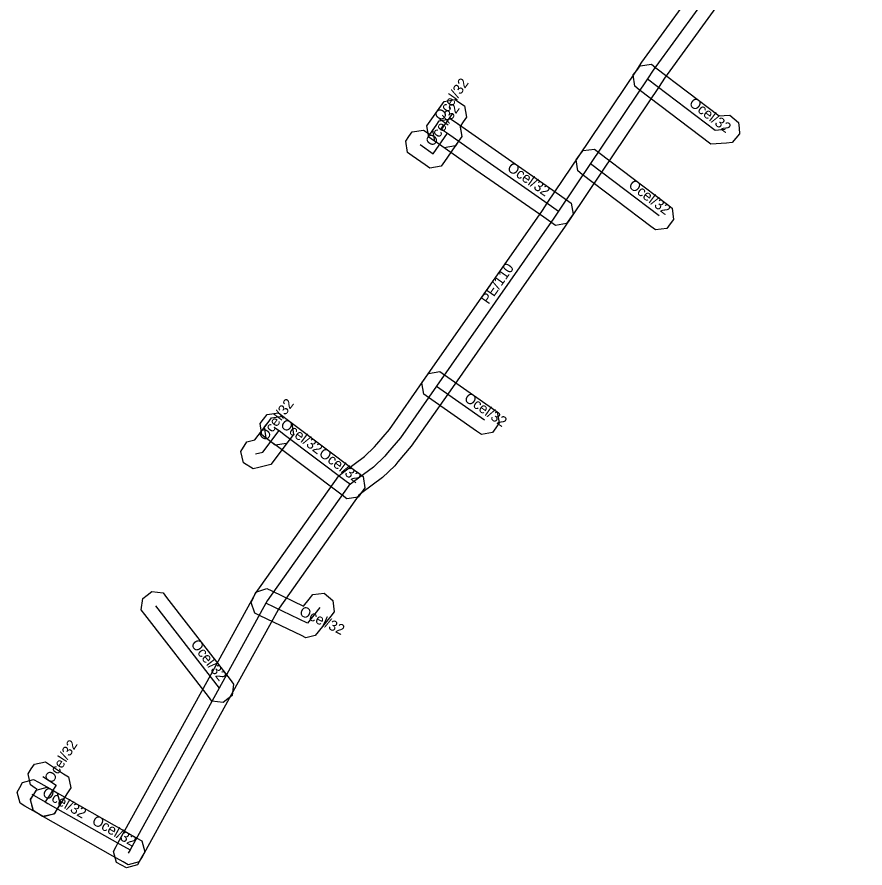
# Model space of a CAD drawing. Extents: x -600607 to -600238, y -1203924 to -1203617.
# Drawn here: x -600383.3 to -600321.7, y -1203772.2 to -1203710.4 of the extents above; entities that cross this region are included whole.
import ezdxf

# ---------------------------------------------------------------- set-up
doc = ezdxf.new("R2010")
doc.units = 0
for name, color, linetype in [('1', 7, 'Continuous'), ('14', 7, 'Continuous'), ('20', 7, 'Continuous')]:
    doc.layers.add(name, color=color, linetype=linetype)

msp = doc.modelspace()

# ---------------------------------------------------------------- linework, layer by layer
at = {"layer": '1'}
msp.add_lwpolyline([(-600329.759, -1203705.902), (-600336.238, -1203714.83), (-600336.638, -1203715.435), (-600340.78, -1203721.588), (-600343.101, -1203725.04), (-600343.466, -1203725.577), (-600351.98, -1203737.763), (-600354.628, -1203741.553), (-600355.596, -1203742.685), (-600355.827, -1203742.962), (-600356.722, -1203743.824), (-600358.216, -1203744.937), (-600358.434, -1203745.106), (-600358.437, -1203745.108), (-600364.232, -1203753.303), (-600364.305, -1203753.434), (-600367.694, -1203759.583), (-600374.177, -1203771.338), (-600374.309, -1203771.572), (-600374.513, -1203771.933), (-600375.311, -1203772.155), (-600375.672, -1203771.951), (-600376.033, -1203771.747), (-600376.255, -1203770.949), (-600376.051, -1203770.588), (-600375.923, -1203770.362), (-600369.446, -1203758.617), (-600366.055, -1203752.466), (-600365.928, -1203752.237), (-600359.886, -1203743.694), (-600359.646, -1203743.514), (-600359.424, -1203743.343), (-600358.018, -1203742.296), (-600357.293, -1203741.598), (-600357.124, -1203741.395), (-600356.212, -1203740.327), (-600353.62, -1203736.617), (-600345.114, -1203724.443), (-600344.759, -1203723.92), (-600342.44, -1203720.472), (-600338.302, -1203714.325), (-600337.882, -1203713.69), (-600331.401, -1203704.758)], dxfattribs=at)
for points in [[(-600337.194, -1203713.833), (-600336.864, -1203714.084), (-600332.269, -1203717.582), (-600331.911, -1203717.553), (-600331.498, -1203717.519), (-600330.867, -1203718.056), (-600330.833, -1203718.469), (-600330.799, -1203718.882), (-600331.336, -1203719.513), (-600331.749, -1203719.547), (-600332.871, -1203719.638), (-600338.076, -1203715.676), (-600338.405, -1203715.425), (-600338.517, -1203714.604), (-600338.266, -1203714.274), (-600338.015, -1203713.945)], [(-600350.851, -1203718.013), (-600351.083, -1203718.344), (-600350.953, -1203719.072), (-600351.19, -1203719.412), (-600351.427, -1203719.752), (-600352.242, -1203719.897), (-600352.582, -1203719.66), (-600353.012, -1203719.36), (-600353.352, -1203719.123), (-600353.425, -1203718.715), (-600353.497, -1203718.306), (-600353.259, -1203717.967), (-600352.489, -1203716.867), (-600352.252, -1203716.527), (-600351.436, -1203716.383), (-600351.097, -1203716.621), (-600350.757, -1203716.858), (-600350.613, -1203717.674)], [(-600353.744, -1203718.604), (-600353.405, -1203718.842), (-600353.287, -1203718.925), (-600352.831, -1203718.269), (-600352.594, -1203717.929), (-600351.779, -1203717.782), (-600351.439, -1203718.019), (-600351.099, -1203718.256), (-600350.952, -1203719.071), (-600351.189, -1203719.411), (-600352.219, -1203720.891), (-600352.457, -1203721.232), (-600352.866, -1203721.305), (-600353.275, -1203721.377), (-600353.615, -1203721.138), (-600354.555, -1203720.478), (-600354.894, -1203720.24), (-600355.036, -1203719.424), (-600354.798, -1203719.085), (-600354.56, -1203718.746)], [(-600351.778, -1203717.783), (-600351.438, -1203718.02), (-600348.788, -1203719.87), (-600343.866, -1203723.301), (-600343.353, -1203723.663), (-600343.015, -1203723.902), (-600342.874, -1203724.719), (-600343.113, -1203725.057), (-600343.352, -1203725.395), (-600344.169, -1203725.536), (-600344.507, -1203725.297), (-600345.014, -1203724.939), (-600349.932, -1203721.51), (-600352.582, -1203719.66), (-600352.922, -1203719.423), (-600353.067, -1203718.608), (-600352.83, -1203718.268), (-600352.593, -1203717.928)], [(-600341.335, -1203719.983), (-600341.005, -1203720.233), (-600336.025, -1203724.013), (-600335.695, -1203724.264), (-600335.583, -1203725.085), (-600335.833, -1203725.415), (-600336.084, -1203725.745), (-600336.905, -1203725.857), (-600337.235, -1203725.607), (-600342.215, -1203721.827), (-600342.545, -1203721.576), (-600342.657, -1203720.755), (-600342.407, -1203720.425), (-600342.156, -1203720.095)], [(-600352.567, -1203736.133), (-600352.227, -1203736.37), (-600348.737, -1203738.81), (-600348.397, -1203739.047), (-600348.253, -1203739.863), (-600348.49, -1203740.203), (-600348.727, -1203740.543), (-600349.543, -1203740.687), (-600349.883, -1203740.45), (-600353.373, -1203738.01), (-600353.713, -1203737.773), (-600353.857, -1203736.957), (-600353.62, -1203736.617), (-600353.383, -1203736.277)], [(-600364.281, -1203739.131), (-600363.95, -1203739.38), (-600363.63, -1203739.62), (-600363.299, -1203739.869), (-600363.181, -1203740.689), (-600363.43, -1203741.02), (-600363.679, -1203741.351), (-600364.499, -1203741.469), (-600364.83, -1203741.22), (-600365.15, -1203740.98), (-600365.481, -1203740.731), (-600365.599, -1203739.911), (-600365.35, -1203739.58), (-600365.101, -1203739.249)], [(-600366.577, -1203741.235), (-600366.174, -1203741.138), (-600365.984, -1203741.092), (-600365.03, -1203739.82), (-600364.781, -1203739.489), (-600363.961, -1203739.371), (-600363.63, -1203739.62), (-600363.299, -1203739.869), (-600363.181, -1203740.689), (-600363.43, -1203741.02), (-600364.816, -1203742.868), (-600365.706, -1203743.082), (-600366.109, -1203743.179), (-600366.815, -1203742.747), (-600366.912, -1203742.344), (-600367.009, -1203741.941)], [(-600363.961, -1203739.371), (-600363.63, -1203739.62), (-600363.15, -1203739.98), (-600358.752, -1203743.278), (-600358.444, -1203743.507), (-600358.111, -1203743.754), (-600357.99, -1203744.573), (-600358.237, -1203744.906), (-600358.484, -1203745.239), (-600359.303, -1203745.36), (-600359.636, -1203745.113), (-600359.948, -1203744.882), (-600364.35, -1203741.58), (-600364.83, -1203741.22), (-600365.161, -1203740.971), (-600365.279, -1203740.151), (-600365.03, -1203739.82), (-600364.781, -1203739.489)], [(-600372.653, -1203752.2), (-600372.4, -1203752.527), (-600367.78, -1203758.487), (-600367.526, -1203758.815), (-600367.63, -1203759.637), (-600367.957, -1203759.89), (-600368.285, -1203760.144), (-600369.107, -1203760.04), (-600369.36, -1203759.713), (-600373.98, -1203753.753), (-600374.234, -1203753.425), (-600374.13, -1203752.603), (-600373.803, -1203752.35), (-600373.475, -1203752.096)], [(-600360.22, -1203753.559), (-600360.478, -1203753.883), (-600361.378, -1203755.013), (-600361.595, -1203755.286), (-600362.275, -1203755.443), (-600362.59, -1203755.293), (-600365.61, -1203753.853), (-600365.984, -1203753.674), (-600366.261, -1203752.894), (-600366.083, -1203752.52), (-600365.904, -1203752.146), (-600365.124, -1203751.869), (-600364.75, -1203752.047), (-600362.447, -1203753.145), (-600362.042, -1203752.637), (-600361.784, -1203752.313), (-600360.961, -1203752.22), (-600360.637, -1203752.478), (-600360.313, -1203752.736)], [(-600381.177, -1203764.457), (-600380.831, -1203764.684), (-600379.871, -1203765.314), (-600379.527, -1203765.54), (-600379.356, -1203766.346), (-600379.579, -1203766.692), (-600380.359, -1203767.902), (-600380.584, -1203768.25), (-600381.394, -1203768.425), (-600381.742, -1203768.201), (-600382.09, -1203767.976), (-600382.265, -1203767.166), (-600382.041, -1203766.818), (-600381.798, -1203766.442), (-600381.929, -1203766.356), (-600382.275, -1203766.129), (-600382.443, -1203765.317), (-600382.216, -1203764.971), (-600381.989, -1203764.625)], [(-600382.044, -1203765.727), (-600381.684, -1203765.932), (-600380.704, -1203766.492), (-600380.344, -1203766.697), (-600380.127, -1203767.496), (-600380.332, -1203767.856), (-600380.537, -1203768.216), (-600381.336, -1203768.433), (-600381.696, -1203768.228), (-600382.676, -1203767.668), (-600383.036, -1203767.463), (-600383.253, -1203766.664), (-600383.048, -1203766.304), (-600382.843, -1203765.944)], [(-600381.057, -1203766.287), (-600380.699, -1203766.495), (-600380.513, -1203766.602), (-600375.293, -1203769.552), (-600374.548, -1203769.985), (-600374.19, -1203770.193), (-600373.977, -1203770.994), (-600374.185, -1203771.352), (-600374.393, -1203771.71), (-600375.194, -1203771.923), (-600375.552, -1203771.715), (-600376.287, -1203771.288), (-600381.507, -1203768.338), (-600381.701, -1203768.225), (-600382.059, -1203768.017), (-600382.273, -1203767.217), (-600382.065, -1203766.859), (-600381.857, -1203766.501)]]:
    msp.add_lwpolyline(points, close=True, dxfattribs=at)
at = {"layer": '14'}
for points in [[(-600321.69, -1203692.03), (-600330.58, -1203705.33), (-600337.06, -1203714.26), (-600337.47, -1203714.88), (-600341.61, -1203721.03), (-600343.93, -1203724.48), (-600344.29, -1203725.01), (-600352.8, -1203737.19), (-600355.42, -1203740.94), (-600356.36, -1203742.04), (-600356.56, -1203742.28), (-600357.37, -1203743.06), (-600358.82, -1203744.14), (-600359.04, -1203744.31), (-600359.16, -1203744.4), (-600365.08, -1203752.77), (-600365.18, -1203752.95), (-600368.57, -1203759.1), (-600375.05, -1203770.85), (-600375.18, -1203771.08)], [(-600337.47, -1203714.88), (-600332.57, -1203718.61), (-600331.83, -1203718.55)], [(-600351.67, -1203717.44), (-600352.44, -1203718.54), (-600352.01, -1203718.84)], [(-600353.98, -1203719.66), (-600353.04, -1203720.32), (-600352.01, -1203718.84)], [(-600352.01, -1203718.84), (-600349.36, -1203720.69), (-600344.44, -1203724.12), (-600343.93, -1203724.48)], [(-600341.61, -1203721.03), (-600336.63, -1203724.81)], [(-600352.8, -1203737.19), (-600349.31, -1203739.63)], [(-600365.94, -1203742.11), (-600365.4, -1203741.98), (-600364.23, -1203740.42)], [(-600364.55, -1203740.18), (-600364.23, -1203740.42)], [(-600364.23, -1203740.42), (-600363.75, -1203740.78), (-600359.35, -1203744.08), (-600359.04, -1203744.31)], [(-600373.19, -1203753.14), (-600368.57, -1203759.1)], [(-600361.26, -1203753.26), (-600362.16, -1203754.39), (-600365.18, -1203752.95)], [(-600381.38, -1203765.52), (-600380.42, -1203766.15), (-600381.2, -1203767.36)], [(-600382.18, -1203766.8), (-600381.2, -1203767.36)], [(-600381.2, -1203767.36), (-600381.01, -1203767.47), (-600375.79, -1203770.42), (-600375.05, -1203770.85)]]:
    msp.add_lwpolyline(points, dxfattribs=at)

# ---------------------------------------------------------------- texts
at = {"layer": '20'}
for s, rotation, p in [('Ocel/32', 55.00798, (-600352.405, -1203718.005)), ('Ocel/32', 322.72072, (-600334.525, -1203716.77)), ('Ocel/32', 55.16417, (-600353.053, -1203719.851)), ('Ocel/32', 325.11755, (-600347.729, -1203721.488)), ('Ocel/32', 322.80019, (-600338.92, -1203722.72)), ('PE/110', 55.05852, (-600349.023, -1203731.298)), ('Ocel/32', 325.04105, (-600350.855, -1203738.21)), ('Ocel/32', 53.1301, (-600365.182, -1203741.222)), ('Ocel/32', 323.1301, (-600364.19, -1203740.1)), ('Ocel/32', 323.1301, (-600361.396, -1203742.196)), ('Ocel/32', 334.5072, (-600362.818, -1203753.781)), ('Ocel/32', 307.78169, (-600370.68, -1203755.92)), ('Ocel/32', 57.19303, (-600380.699, -1203766.072)), ('Ocel/32', 330.25512, (-600381.49, -1203766.88)), ('Ocel/32', 330.52773, (-600377.879, -1203768.926))]:
    msp.add_text(s, height=0.75, rotation=rotation, dxfattribs=at).set_placement(p)

doc.saveas('drawing.dxf')
